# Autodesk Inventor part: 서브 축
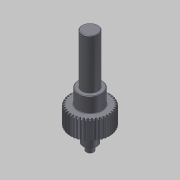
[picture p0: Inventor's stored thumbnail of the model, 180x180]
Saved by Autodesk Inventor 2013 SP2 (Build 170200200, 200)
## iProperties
Created: 2016-02
Part Number: 서브 축
Material: 강철, 연강
Document SubType Name: Modeling
Designer: mdu
Categories: <?xml version="1.0" encoding="UTF-16"?> <MemberInstance><Categories><FamilyTemplate><FamilyTemplateParameter ValueType="xs:double" Id="1" ObjectReferenceKey="da
Density: 7.86 g/cm^3
CustomPartVersion: 1
Author: mdu
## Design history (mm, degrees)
sketch "Sketch1"
  geometry: C1 r 21 at (0, 0)
  constraints: 1 centre point
  dimensions: "d0" = 42 diameter of C1 (= da_da)
extrude "Extrusion1" new body sketch "Sketch1" distance "d1" = 20 (= da_b); taper "d2" = 0 deg
workplane "Work Plane2"
feature "피치 지름" dims "d4" = 10, "d5" = 0
workplane "Work Plane8"
workplane "Work Plane9"
chamfer "모따기1" distance "d49" = 1; stored, may be unused: second distance "d50" = 2, angle "d51" = 45 deg
sketch "스케치3"
  geometry: C1 r 12.5 at (0, 0); 1 further point
  constraints: 1 centre point, 1 coincident
  dimensions: "d52" = 25 diameter of C1
extrude "돌출2" join sketch "스케치3" distance "d53" = 16; taper "d54" = 0 deg
sketch "스케치4"
  geometry: C1 r 8.5 at (0, 0); 1 further point
  constraints: 1 centre point, 1 coincident
  dimensions: "d55" = 17 diameter of C1
extrude "돌출3" join sketch "스케치4" distance "d56" = 53; taper "d57" = 0 deg
sketch "스케치5"
  geometry: C1 r 7.5 at (0, 0); 1 further point
  constraints: 1 centre point, 1 coincident
  dimensions: "d62" = 15 diameter of C1
extrude "돌출4" join sketch "스케치5" distance "d63" = 16; taper "d64" = 0 deg
sketch "스케치6"
  geometry: C1 r 4 at (0, 0); 1 further point
  constraints: 1 centre point, 1 coincident
  dimensions: "d65" = 8 diameter of C1
extrude "돌출5" join sketch "스케치6" distance "d66" = 7; taper "d67" = 0 deg
chamfer "모따기2" distance "d58" = 0.5; stored, may be unused: second distance "d59" = 2, angle "d60" = 45 deg
fillet "모깎기1" dims "d61" = 0.5
feature "스퍼 기어" dims "da_b" = 20, "da_d" = 40, "da_aw" = 31, "da_da" = 42, "da_df" = 37.5, "da_dw" = 40, angle "da_beta" = 0 deg, "da_lefttooth" = 0, "da_righttooth" = 0
body "Solid1"
sketch "Sketch2"
  geometry: C1 r 21 at (0, 0) reference; C2 r 20 at (0, 0)
  constraints: 1 centre point, 1 coincident
  dimensions: "d3" = 40 diameter of C2 (= da_dw)
body "Srf1"
other parameters: "d16" = 31 (= da_aw), "d17" = 0, "d34" = 4.5 deg (computed from da_z), "d39" = 0, "d41" = 0, "d43" = 31 (= da_aw), "d46" = 31 (= da_aw), "d47" = 0, "d48" = 0
